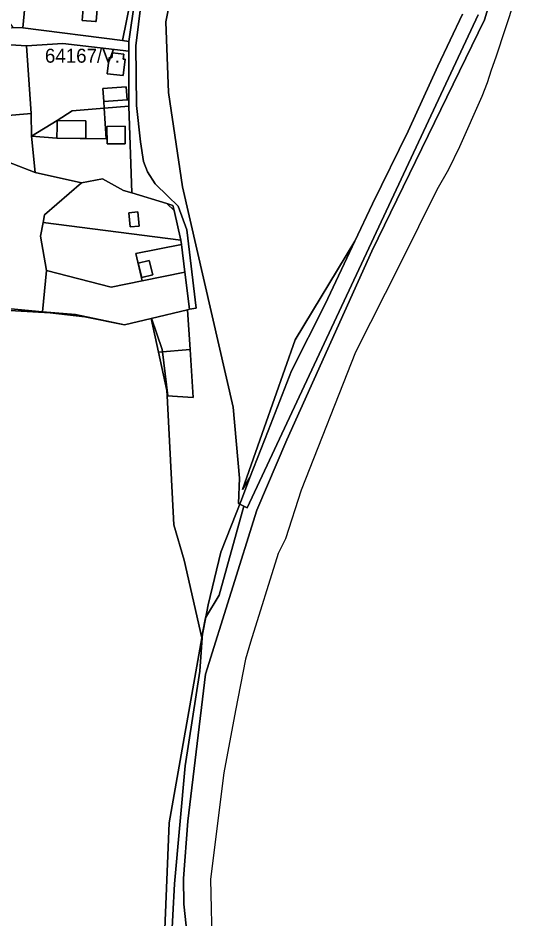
# Model space of a CAD drawing. Extents: x -502026 to -497664, y -1143484 to -1138019.
# Drawn here: x -498176 to -497882, y -1141619 to -1141104 of the extents above; entities that cross this region are included whole.
import ezdxf

# ---------------------------------------------------------------- set-up
doc = ezdxf.new("R2010")
doc.units = 0
for name, color, linetype in [('25', 7, 'Continuous'), ('31', 7, 'Continuous'), ('37', 7, 'Continuous'), ('43', 7, 'Continuous'), ('49', 7, 'Continuous'), ('55', 7, 'Continuous'), ('62', 7, 'Continuous'), ('7', 7, 'Continuous')]:
    doc.layers.add(name, color=color, linetype=linetype)

msp = doc.modelspace()

# ---------------------------------------------------------------- linework, layer by layer
at = {"layer": '25'}
for points in [[(-498172.98, -1141080.96), (-498171.74, -1141089.31), (-498173.69, -1141109.45), (-498179.19, -1141109.35), (-498202.54, -1141075.9), (-498188.4, -1141055.94), (-498178.36, -1141044.85)], [(-498148.18, -1141090.62), (-498138.63, -1141091.11), (-498138.65, -1141091.36), (-498139.71, -1141105.25), (-498132.13, -1141105.91), (-498131.88, -1141105.93), (-498130.85, -1141094.17), (-498130.66, -1141092.02), (-498130.64, -1141091.77), (-498112.07, -1141093.05), (-498116.81, -1141116.75), (-498173.69, -1141109.45), (-498171.74, -1141089.31)], [(-498113.18, -1141122.79), (-498113.11, -1141150.63), (-498114.14, -1141150.71), (-498114.69, -1141143.2), (-498128.03, -1141144.17), (-498127.48, -1141151.69), (-498127.22, -1141155.49), (-498145.51, -1141157.01), (-498154.1, -1141162.44), (-498168.81, -1141171.48), (-498168.9, -1141158.45), (-498171.53, -1141119.83), (-498150.8, -1141118.41)], [(-498171.53, -1141119.83), (-498168.9, -1141158.45), (-498170.98, -1141158.69), (-498202.59, -1141161.44), (-498226.74, -1141149.75), (-498227.94, -1141138.12), (-498187.47, -1141138.9), (-498187.08, -1141118.91)], [(-498116.01, -1141124.53), (-498122.44, -1141123.81), (-498122.84, -1141126.74), (-498124.45, -1141126.57), (-498125.44, -1141135.77), (-498116.34, -1141136.75), (-498115.3, -1141127.52), (-498116.34, -1141127.4)], [(-498168.81, -1141171.48), (-498166.57, -1141192.19), (-498192.38, -1141182.26), (-498202.3, -1141182.13), (-498202.48, -1141180.77), (-498198.29, -1141180.22), (-498198.31, -1141180.11), (-498195.47, -1141179.73), (-498196.59, -1141171.81), (-498199.4, -1141172.19), (-498199.42, -1141172.08), (-498203.53, -1141172.62), (-498204.81, -1141162.71), (-498211.34, -1141163.53), (-498211.51, -1141162.22), (-498202.59, -1141161.44), (-498170.98, -1141158.69), (-498168.9, -1141158.45)], [(-498137.78, -1141172.88), (-498137.64, -1141162.68), (-498154.1, -1141162.44), (-498145.51, -1141157.01), (-498127.22, -1141155.49), (-498126.04, -1141173.04)], [(-498154.25, -1141172.64), (-498168.81, -1141171.48), (-498154.1, -1141162.44), (-498154.15, -1141165.77)], [(-498111.43, -1141203.93), (-498091.49, -1141210.05), (-498087.32, -1141213.89), (-498083.44, -1141230.92), (-498162.14, -1141220.93), (-498161.31, -1141216.42), (-498140.17, -1141198.25), (-498128.15, -1141195.96), (-498116.21, -1141202.46)], [(-498107.16, -1141222.91), (-498107.9, -1141214.72), (-498113.17, -1141215.28), (-498112.31, -1141223.38)], [(-498083.44, -1141230.92), (-498083.09, -1141233.44), (-498109.06, -1141238.65), (-498105.61, -1141254.26), (-498123.19, -1141257.75), (-498160.2, -1141248.38), (-498163.59, -1141228.75), (-498162.14, -1141220.93)], [(-498081.13, -1141249.31), (-498105.61, -1141254.26), (-498109.06, -1141238.65), (-498083.09, -1141233.44)], [(-498099.38, -1141250.77), (-498101.48, -1141242.57), (-498107.71, -1141244.16), (-498105.63, -1141252.36)], [(-498105.61, -1141254.26), (-498081.13, -1141249.31), (-498078.55, -1141270.48), (-498079.54, -1141270.72), (-498100.31, -1141275.68), (-498115.7, -1141279.46), (-498143.69, -1141273.54), (-498162.39, -1141271.86), (-498160.2, -1141248.38), (-498123.19, -1141257.75)]]:
    msp.add_lwpolyline(points, close=True, dxfattribs=at)
at = {"layer": '31'}
msp.add_lwpolyline([(-498213.6, -1141181.91), (-498208.99, -1141182.05), (-498202.3, -1141182.13), (-498192.38, -1141182.26), (-498166.57, -1141192.19), (-498140.17, -1141198.25), (-498161.31, -1141216.42), (-498162.14, -1141220.93), (-498163.59, -1141228.75), (-498160.2, -1141248.38), (-498162.39, -1141271.86), (-498186.41, -1141269.59), (-498188.24, -1141251.77), (-498202.68, -1141245.53), (-498211.91, -1141236.53), (-498234.18, -1141226.31), (-498232.45, -1141217.73), (-498232.35, -1141212.43), (-498230.37, -1141212.92), (-498226.47, -1141197.2), (-498230.85, -1141196.15), (-498227.64, -1141181.47)], close=True, dxfattribs=at)
at = {"layer": '37'}
for points in [[(-498111.43, -1141203.93), (-498116.21, -1141202.46), (-498128.15, -1141195.96), (-498140.17, -1141198.25), (-498166.57, -1141192.19), (-498168.81, -1141171.48), (-498154.25, -1141172.64), (-498140.98, -1141172.83), (-498137.78, -1141172.88), (-498126.04, -1141173.04), (-498127.22, -1141155.49), (-498113.1, -1141154.31)], [(-498113.1, -1141154.31), (-498127.22, -1141155.49), (-498127.48, -1141151.69), (-498114.14, -1141150.71), (-498113.11, -1141150.63)], [(-498115.17, -1141175.79), (-498115.31, -1141165.76), (-498125.62, -1141165.88), (-498125.49, -1141175.92)]]:
    msp.add_lwpolyline(points, close=True, dxfattribs=at)
at = {"layer": '43'}
msp.add_lwpolyline([(-498186.41, -1141269.59), (-498162.39, -1141271.86), (-498143.69, -1141273.54), (-498115.7, -1141279.46), (-498100.31, -1141275.68), (-498096.16, -1141294.92), (-498091.41, -1141316.97), (-498091.27, -1141319.9), (-498087.47, -1141393.76), (-498081.5, -1141414.01), (-498071.48, -1141458.36), (-498090.08, -1141564.22), (-498093.13, -1141638.94)], dxfattribs=at)
at = {"layer": '49'}
for points in [[(-498079.89, -1141628.43), (-498081.67, -1141610.69), (-498081.94, -1141596.08), (-498079.48, -1141563.17), (-498069.25, -1141479.07), (-498039.94, -1141385.29), (-498022.77, -1141345.12), (-497974.26, -1141237.33), (-497909.86, -1141104.95), (-497895.56, -1141057.44)], [(-497882.24, -1141061.82), (-497903.42, -1141126.29), (-497906.06, -1141133.81), (-497908.5, -1141141), (-497911.36, -1141148.73), (-497924.16, -1141177.53), (-497930.44, -1141190.51), (-497937.08, -1141202.15), (-497958.04, -1141244.5), (-497983.66, -1141295.03), (-498014.69, -1141373.89), (-498023.58, -1141401.84), (-498027.82, -1141410.2), (-498043.69, -1141460.8), (-498046.55, -1141470.54), (-498052.15, -1141500), (-498058.92, -1141535.59), (-498066.45, -1141596.33), (-498065.44, -1141638.73)]]:
    msp.add_lwpolyline(points, dxfattribs=at)
at = {"layer": '55'}
for points in [[(-497895.56, -1141057.44), (-497909.86, -1141104.95), (-497974.26, -1141237.33), (-498022.77, -1141345.12), (-498039.94, -1141385.29), (-498069.25, -1141479.07), (-498079.48, -1141563.17), (-498081.94, -1141596.08), (-498081.67, -1141610.69), (-498079.89, -1141628.43)], [(-498106.07, -1141095.04), (-498109.11, -1141119.87), (-498108.84, -1141153.98), (-498106.55, -1141174.75), (-498104.84, -1141185.91), (-498102.41, -1141191.82), (-498098.14, -1141198.81), (-498090.9, -1141205.7), (-498084.99, -1141211.46), (-498079.95, -1141225), (-498074.63, -1141269.92), (-498078.55, -1141270.48), (-498081.13, -1141249.31), (-498083.09, -1141233.44), (-498083.44, -1141230.92), (-498087.32, -1141213.89), (-498087.97, -1141211.13), (-498091.49, -1141210.05), (-498111.43, -1141203.93), (-498113.1, -1141154.31), (-498113.11, -1141150.63), (-498113.18, -1141122.79), (-498113.13, -1141117.32), (-498109.78, -1141093.24)], [(-498093.13, -1141638.94), (-498090.08, -1141564.22), (-498071.48, -1141458.36), (-498067.83, -1141439.49), (-498060.66, -1141409.3), (-498048.79, -1141379.42), (-498043.93, -1141366.76), (-498033.62, -1141339.9), (-498020.22, -1141305.67), (-498000.94, -1141267.61), (-497983.96, -1141231.47), (-497974.01, -1141210.14), (-497953.58, -1141168.63), (-497936.6, -1141131.47), (-497922.56, -1141101.71)]]:
    msp.add_lwpolyline(points, dxfattribs=at)
for points in [[(-498130.64, -1141091.77), (-498130.66, -1141092.02), (-498130.85, -1141094.17), (-498131.88, -1141105.93), (-498132.13, -1141105.91), (-498139.71, -1141105.25), (-498138.65, -1141091.36), (-498138.63, -1141091.11)], [(-498109.78, -1141093.24), (-498113.13, -1141117.32), (-498116.81, -1141116.75), (-498112.07, -1141093.05)], [(-498173.69, -1141109.45), (-498116.81, -1141116.75), (-498113.13, -1141117.32), (-498113.18, -1141122.79), (-498150.8, -1141118.41), (-498171.53, -1141119.83), (-498187.08, -1141118.91), (-498190.49, -1141118.8), (-498227.71, -1141116.93), (-498224.74, -1141112.39), (-498203.8, -1141113.52), (-498179.19, -1141109.35)], [(-498116.01, -1141124.53), (-498116.34, -1141127.4), (-498115.3, -1141127.52), (-498116.34, -1141136.75), (-498125.44, -1141135.77), (-498124.45, -1141126.57), (-498122.84, -1141126.74), (-498122.44, -1141123.81)], [(-498114.14, -1141150.71), (-498127.48, -1141151.69), (-498128.03, -1141144.17), (-498114.69, -1141143.2)], [(-498137.78, -1141172.88), (-498140.98, -1141172.83), (-498154.25, -1141172.64), (-498154.15, -1141165.77), (-498154.1, -1141162.44), (-498137.64, -1141162.68)], [(-498115.17, -1141175.79), (-498125.49, -1141175.92), (-498125.62, -1141165.88), (-498115.31, -1141165.76)], [(-498087.32, -1141213.89), (-498091.49, -1141210.05), (-498087.97, -1141211.13)], [(-498107.16, -1141222.91), (-498112.31, -1141223.38), (-498113.17, -1141215.28), (-498107.9, -1141214.72)], [(-498043.93, -1141366.76), (-498048.14, -1141373.58), (-498035.73, -1141338.3), (-498018.11, -1141287.98), (-497983.96, -1141231.47), (-498000.94, -1141267.61), (-498020.22, -1141305.67), (-498033.62, -1141339.9)], [(-498099.38, -1141250.77), (-498105.63, -1141252.36), (-498107.71, -1141244.16), (-498101.48, -1141242.57)], [(-498078.06, -1141293.56), (-498096.16, -1141294.92), (-498100.31, -1141275.68), (-498079.54, -1141270.72)], [(-498091.27, -1141319.9), (-498091.41, -1141316.97), (-498096.16, -1141294.92), (-498078.06, -1141293.56), (-498076.29, -1141320.9)]]:
    msp.add_lwpolyline(points, close=True, dxfattribs=at)
at = {"layer": '62'}
for points in [[(-498078.5, -1141039), (-498092, -1141106), (-498090.5, -1141146.5), (-498082.5, -1141200.5), (-498053.5, -1141326.5), (-498050, -1141367), (-498050.5, -1141381.5), (-498049.76, -1141381.87), (-498047.5, -1141383), (-498061.5, -1141434), (-498069.27, -1141446.96), (-498070.97, -1141455.76), (-498071.48, -1141458.36), (-498081.5, -1141414.01), (-498087.47, -1141393.76), (-498091.27, -1141319.9), (-498090.84, -1141319.93), (-498093.85, -1141294.75), (-498094, -1141293.5), (-498100.11, -1141275.63), (-498100.31, -1141275.68), (-498115.7, -1141279.46), (-498138.21, -1141274.7), (-498158, -1141272.5), (-498184.5, -1141271)], [(-497913.5, -1141102), (-498045.5, -1141384), (-498047.5, -1141383), (-498049.76, -1141381.87), (-498050.5, -1141381.5), (-498050, -1141367), (-498053.5, -1141326.5), (-498082.5, -1141200.5), (-498090.5, -1141146.5), (-498092, -1141106), (-498078.5, -1141039)], [(-497882.24, -1141061.82), (-497903.42, -1141126.29), (-497906.06, -1141133.81), (-497908.5, -1141141), (-497911.36, -1141148.73), (-497924.16, -1141177.53), (-497930.44, -1141190.51), (-497937.08, -1141202.15), (-497958.04, -1141244.5), (-497983.66, -1141295.03), (-498014.69, -1141373.89), (-498023.58, -1141401.84), (-498027.82, -1141410.2), (-498043.69, -1141460.8), (-498046.55, -1141470.54), (-498052.15, -1141500), (-498058.92, -1141535.59), (-498066.45, -1141596.33), (-498065.44, -1141638.73)], [(-498089, -1141635), (-498087, -1141599), (-498081, -1141531.5), (-498072.5, -1141477.5), (-498070.97, -1141455.76), (-498069.27, -1141446.96), (-498061.5, -1141434), (-498047.5, -1141383), (-498045.5, -1141384), (-497913.5, -1141102)], [(-498184.5, -1141271), (-498158, -1141272.5), (-498138.21, -1141274.7), (-498115.7, -1141279.46), (-498100.31, -1141275.68), (-498100.11, -1141275.63), (-498094, -1141293.5), (-498093.85, -1141294.75), (-498090.84, -1141319.93), (-498091.27, -1141319.9), (-498087.47, -1141393.76), (-498081.5, -1141414.01), (-498071.48, -1141458.36), (-498070.97, -1141455.76), (-498072.5, -1141477.5), (-498081, -1141531.5), (-498087, -1141599), (-498089, -1141635)]]:
    msp.add_lwpolyline(points, dxfattribs=at)
at = {"layer": '7'}
msp.add_lwpolyline([(-497922.56, -1141101.71), (-497936.6, -1141131.47), (-497953.58, -1141168.63), (-497974.01, -1141210.14), (-497983.96, -1141231.47), (-498018.11, -1141287.98), (-498035.73, -1141338.3), (-498048.14, -1141373.58), (-498043.93, -1141366.76), (-498048.79, -1141379.42), (-498060.66, -1141409.3), (-498067.83, -1141439.49), (-498071.48, -1141458.36), (-498081.5, -1141414.01), (-498087.47, -1141393.76), (-498091.27, -1141319.9), (-498076.29, -1141320.9), (-498078.06, -1141293.56), (-498079.54, -1141270.72), (-498078.55, -1141270.48), (-498074.63, -1141269.92), (-498079.95, -1141225), (-498084.99, -1141211.46), (-498090.9, -1141205.7), (-498098.14, -1141198.81), (-498102.41, -1141191.82), (-498104.84, -1141185.91), (-498106.55, -1141174.75), (-498108.84, -1141153.98), (-498109.11, -1141119.87), (-498106.07, -1141095.04)], dxfattribs=at)

# ---------------------------------------------------------------- texts
at = {"layer": '62'}
msp.add_text('64167/V.', height=8, dxfattribs=at).set_placement((-498161.08, -1141129.45))

doc.saveas('drawing.dxf')
